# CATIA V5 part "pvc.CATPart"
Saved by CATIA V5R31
Part number: pvc
Bounding box of the stored display mesh (mm): x -24.75 to 24.75, y -24.57 to 24.57, z 0 to 500
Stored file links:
  C:\Users\189361\Desktop\piezas del comedero\piezas del comedero\pvc.CATPart
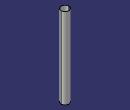
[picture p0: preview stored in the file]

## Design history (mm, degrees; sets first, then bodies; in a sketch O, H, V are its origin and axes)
Body1 (main body)
  Sketch1 on xy-plane, origin (0, 0, 0), H (1, 0, 0), V (0, 1, 0)
    circle A1 centre (0, 0) radius 24.75
    circle A2 centre (0, 0) radius 23.5
    radius A1 = 24.75
    radius A2 = 23.5
  Pad1: profile Sketch1, direction (0, 0, 1), length 500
